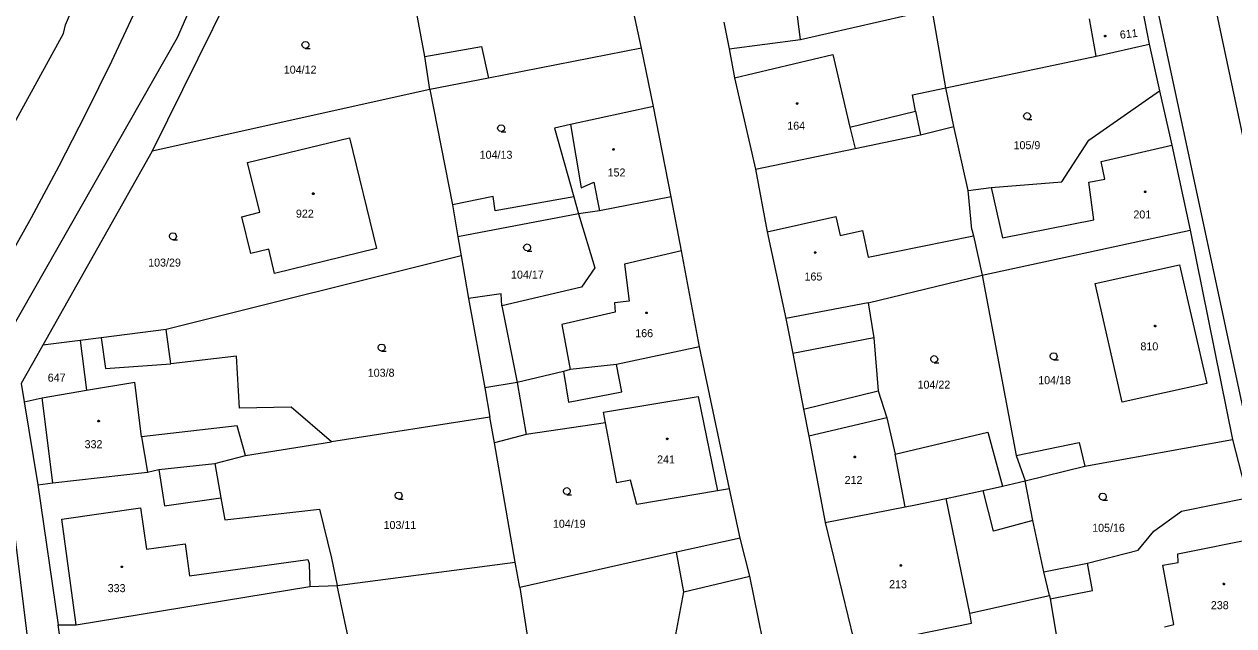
# Model space of a CAD drawing. Extents: x -757994 to -755874, y -1047691 to -1046119.
# Drawn here: x -756803.8 to -756675.3, y -1047083.2 to -1047019.3 of the extents above; entities that cross this region are included whole.
import ezdxf

# ---------------------------------------------------------------- set-up
doc = ezdxf.new("R2010")
doc.units = 0
doc.layers.add('katastrální mapa', color=7, linetype='Continuous')

msp = doc.modelspace()

# ---------------------------------------------------------------- linework, layer by layer
at = {"layer": 'katastrální mapa'}
for p, q in [((-756701.95, -1046901.14), (-756668.39, -1047059.3)), ((-756707.71, -1046903.74), (-756665.23, -1047102.74)), ((-756799.4, -1047019.41), (-756785.81, -1046987.62)), ((-756776.48, -1046995.54), (-756787.52, -1047020.76)), ((-756780.89, -1047014.02), (-756790.18, -1047032.81)), ((-756761.2, -1047022.76), (-756762.53, -1047015.73)), ((-756738.2, -1047021.87), (-756739.44, -1047016.08)), ((-756721.32, -1047020.94), (-756721.78, -1047017.37)), ((-756721.32, -1047020.94), (-756707.32, -1047017.76)), ((-756705.85, -1047026.09), (-756707.32, -1047017.76)), ((-756685, -1047017.62), (-756684.26, -1047021.44)), ((-756799.59, -1047020.32), (-756799.4, -1047019.41)), ((-756729.44, -1047019.12), (-756728.9, -1047021.94)), ((-756689.9, -1047022.72), (-756690.59, -1047018.75)), ((-756809.98, -1047039.19), (-756799.59, -1047020.32)), ((-756787.52, -1047020.76), (-756807.3, -1047055.47)), ((-756761.2, -1047022.76), (-756755.2, -1047021.69)), ((-756755.2, -1047021.69), (-756754.46, -1047025.07)), ((-756738.2, -1047021.87), (-756754.46, -1047025.07)), ((-756736.91, -1047028.06), (-756738.2, -1047021.87)), ((-756728.9, -1047021.94), (-756721.32, -1047020.94)), ((-756728.9, -1047021.94), (-756728.31, -1047025.02)), ((-756689.9, -1047022.72), (-756684.26, -1047021.44)), ((-756684.26, -1047021.44), (-756683.15, -1047026.41)), ((-756760.69, -1047026.26), (-756761.2, -1047022.76)), ((-756728.31, -1047025.02), (-756717.88, -1047022.55)), ((-756717.88, -1047022.55), (-756716.05, -1047030.25)), ((-756705.85, -1047026.09), (-756689.9, -1047022.72)), ((-756754.46, -1047025.07), (-756760.69, -1047026.26)), ((-756728.31, -1047025.02), (-756726.09, -1047034.74)), ((-756760.69, -1047026.26), (-756790.18, -1047032.81)), ((-756760.69, -1047026.26), (-756758.27, -1047038.5)), ((-756709.39, -1047026.83), (-756705.85, -1047026.09)), ((-756709.08, -1047028.56), (-756709.39, -1047026.83)), ((-756705, -1047030.19), (-756705.85, -1047026.09)), ((-756690.67, -1047031.63), (-756683.15, -1047026.41)), ((-756683.15, -1047026.41), (-756681.86, -1047032.17)), ((-756736.91, -1047028.06), (-756745.74, -1047029.99)), ((-756735.05, -1047037.66), (-756736.91, -1047028.06)), ((-756716.05, -1047030.25), (-756709.08, -1047028.56)), ((-756709.08, -1047028.56), (-756708.55, -1047031.06)), ((-756745.74, -1047029.99), (-756747.44, -1047030.36)), ((-756747.44, -1047030.36), (-756745.39, -1047037.65)), ((-756745.74, -1047029.99), (-756744.61, -1047036.71)), ((-756716.05, -1047030.25), (-756715.51, -1047032.52)), ((-756715.51, -1047032.52), (-756708.55, -1047031.06)), ((-756708.55, -1047031.06), (-756705, -1047030.19)), ((-756703.5, -1047037), (-756705, -1047030.19)), ((-756780.04, -1047034.01), (-756769.22, -1047031.38)), ((-756769.22, -1047031.38), (-756766.35, -1047043.16)), ((-756693.55, -1047036.07), (-756690.67, -1047031.63)), ((-756689.37, -1047033.91), (-756681.86, -1047032.17)), ((-756681.86, -1047032.17), (-756679.91, -1047041.22)), ((-756790.18, -1047032.81), (-756801.8, -1047053.43)), ((-756726.09, -1047034.74), (-756715.51, -1047032.52)), ((-756778.76, -1047039.3), (-756780.04, -1047034.01)), ((-756726.09, -1047034.74), (-756724.84, -1047041.38)), ((-756688.98, -1047035.8), (-756689.37, -1047033.91)), ((-756744.61, -1047036.71), (-756743.27, -1047036.11)), ((-756743.27, -1047036.11), (-756742.67, -1047039.16)), ((-756701.05, -1047036.67), (-756693.55, -1047036.07)), ((-756690.67, -1047036.11), (-756688.98, -1047035.8)), ((-756690.14, -1047040.09), (-756690.67, -1047036.11)), ((-756703.5, -1047037), (-756701.05, -1047036.67)), ((-756703.1, -1047041.13), (-756703.5, -1047037)), ((-756701.05, -1047036.67), (-756699.84, -1047042.02)), ((-756753.96, -1047037.61), (-756758.27, -1047038.5)), ((-756758.27, -1047038.5), (-756757.72, -1047041.91)), ((-756753.76, -1047039.14), (-756753.96, -1047037.61)), ((-756745.39, -1047037.65), (-756753.76, -1047039.14)), ((-756745.39, -1047037.65), (-756744.88, -1047039.46)), ((-756735.05, -1047037.66), (-756742.67, -1047039.16)), ((-756733.96, -1047043.4), (-756735.05, -1047037.66)), ((-756780.65, -1047039.77), (-756778.76, -1047039.3)), ((-756779.69, -1047043.67), (-756780.65, -1047039.77)), ((-756744.88, -1047039.46), (-756757.72, -1047041.91)), ((-756742.67, -1047039.16), (-756744.88, -1047039.46)), ((-756744.88, -1047039.46), (-756743.16, -1047045.2)), ((-756724.84, -1047041.38), (-756717.55, -1047039.74)), ((-756717.55, -1047039.74), (-756717.08, -1047041.76)), ((-756699.84, -1047042.02), (-756690.14, -1047040.09)), ((-756724.84, -1047041.38), (-756722.85, -1047050.58)), ((-756717.08, -1047041.76), (-756714.73, -1047041.25)), ((-756714.73, -1047041.25), (-756714.13, -1047044.07)), ((-756703.1, -1047041.13), (-756702.94, -1047041.82)), ((-756701.99, -1047045.97), (-756679.91, -1047041.22)), ((-756679.91, -1047041.22), (-756675.41, -1047063.42)), ((-756757.72, -1047041.91), (-756757.37, -1047043.94)), ((-756714.13, -1047044.07), (-756702.94, -1047041.82)), ((-756702.94, -1047041.82), (-756701.99, -1047045.97)), ((-756757.37, -1047043.94), (-756788.69, -1047051.74)), ((-756777.8, -1047043.21), (-756779.69, -1047043.67)), ((-756777.17, -1047045.79), (-756777.8, -1047043.21)), ((-756766.35, -1047043.16), (-756777.17, -1047045.79)), ((-756757.37, -1047043.94), (-756756.58, -1047048.46)), ((-756733.96, -1047043.4), (-756739.99, -1047044.8)), ((-756732.03, -1047053.61), (-756733.96, -1047043.4)), ((-756743.16, -1047045.2), (-756744.58, -1047047.24)), ((-756739.99, -1047044.8), (-756739.49, -1047048.73)), ((-756689.99, -1047046.88), (-756681.04, -1047044.88)), ((-756681.04, -1047044.88), (-756678.15, -1047057.5)), ((-756714.12, -1047048.91), (-756701.99, -1047045.97)), ((-756701.99, -1047045.97), (-756698.39, -1047065.15)), ((-756744.58, -1047047.24), (-756753.04, -1047049.24)), ((-756687.14, -1047059.47), (-756689.99, -1047046.88)), ((-756753.12, -1047047.95), (-756756.58, -1047048.46)), ((-756756.58, -1047048.46), (-756754.84, -1047057.95)), ((-756753.04, -1047049.24), (-756753.12, -1047047.95)), ((-756739.49, -1047048.73), (-756741.06, -1047048.93)), ((-756741.06, -1047048.93), (-756741.01, -1047049.93)), ((-756714.12, -1047048.91), (-756722.85, -1047050.58)), ((-756714.12, -1047048.91), (-756713.5, -1047052.65)), ((-756753.04, -1047049.24), (-756751.42, -1047057.37)), ((-756741.01, -1047049.93), (-756746.65, -1047051.21)), ((-756746.65, -1047051.21), (-756745.78, -1047056)), ((-756722.85, -1047050.58), (-756722.13, -1047054.31)), ((-756797.83, -1047052.92), (-756801.8, -1047053.43)), ((-756795.61, -1047052.63), (-756797.83, -1047052.92)), ((-756797.83, -1047052.92), (-756797.15, -1047058.21)), ((-756788.69, -1047051.74), (-756795.61, -1047052.63)), ((-756795.61, -1047052.63), (-756795.14, -1047055.89)), ((-756788.19, -1047055.4), (-756788.69, -1047051.74)), ((-756713.5, -1047052.65), (-756722.13, -1047054.31)), ((-756713.5, -1047052.65), (-756713.05, -1047058.26)), ((-756801.8, -1047053.43), (-756802.44, -1047054.55)), ((-756732.03, -1047053.61), (-756740.84, -1047055.46)), ((-756728.84, -1047068.66), (-756732.03, -1047053.61)), ((-756802.44, -1047054.55), (-756804.09, -1047057.48)), ((-756795.14, -1047055.89), (-756788.19, -1047055.4)), ((-756781.24, -1047054.59), (-756788.19, -1047055.4)), ((-756780.92, -1047060.12), (-756781.24, -1047054.59)), ((-756740.84, -1047055.46), (-756745.78, -1047056)), ((-756740.28, -1047058.39), (-756740.84, -1047055.46)), ((-756722.13, -1047054.31), (-756720.99, -1047060.2)), ((-756746.5, -1047056.22), (-756751.42, -1047057.37)), ((-756745.78, -1047056), (-756746.5, -1047056.22)), ((-756746.5, -1047056.22), (-756745.95, -1047059.48)), ((-756804.09, -1047057.48), (-756803.77, -1047059.45)), ((-756797.15, -1047058.21), (-756792.02, -1047057.33)), ((-756791.33, -1047063.16), (-756792.02, -1047057.33)), ((-756751.42, -1047057.37), (-756754.84, -1047057.95)), ((-756754.84, -1047057.95), (-756754.32, -1047061.05)), ((-756751.42, -1047057.37), (-756750.45, -1047062.92)), ((-756678.15, -1047057.5), (-756687.14, -1047059.47)), ((-756803.77, -1047059.45), (-756801.87, -1047059.02)), ((-756801.87, -1047059.02), (-756797.15, -1047058.21)), ((-756800.73, -1047068.04), (-756801.87, -1047059.02)), ((-756745.95, -1047059.48), (-756740.28, -1047058.39)), ((-756742.22, -1047060.54), (-756732.17, -1047058.86)), ((-756732.17, -1047058.86), (-756730.12, -1047068.88)), ((-756720.99, -1047060.2), (-756713.05, -1047058.26)), ((-756713.05, -1047058.26), (-756712.13, -1047061.13)), ((-756803.77, -1047059.45), (-756802.33, -1047068.26)), ((-756775.43, -1047059.99), (-756780.92, -1047060.12)), ((-756771.13, -1047063.67), (-756775.43, -1047059.99)), ((-756742.01, -1047061.67), (-756742.22, -1047060.54)), ((-756720.99, -1047060.2), (-756720.43, -1047063.09)), ((-756797.61, -1047131.45), (-756806.3, -1047061.1)), ((-756754.32, -1047061.05), (-756771.13, -1047063.67)), ((-756753.8, -1047063.79), (-756754.32, -1047061.05)), ((-756742.01, -1047061.67), (-756750.45, -1047062.92)), ((-756740.82, -1047068.03), (-756742.01, -1047061.67)), ((-756712.13, -1047061.13), (-756720.43, -1047063.09)), ((-756712.13, -1047061.13), (-756711.24, -1047065)), ((-756781.17, -1047061.99), (-756791.33, -1047063.16)), ((-756791.33, -1047063.16), (-756790.67, -1047066.9)), ((-756780.25, -1047065.14), (-756781.17, -1047061.99)), ((-756750.45, -1047062.92), (-756753.8, -1047063.79)), ((-756720.43, -1047063.09), (-756718.67, -1047072.24)), ((-756711.24, -1047065), (-756701.41, -1047062.67)), ((-756701.41, -1047062.67), (-756699.84, -1047068.39)), ((-756780.25, -1047065.14), (-756771.13, -1047063.67)), ((-756751.62, -1047076.46), (-756753.8, -1047063.79)), ((-756698.39, -1047065.15), (-756691.71, -1047063.77)), ((-756691.71, -1047063.77), (-756691.1, -1047066.27)), ((-756691.1, -1047066.27), (-756675.41, -1047063.42)), ((-756675.41, -1047063.42), (-756673.83, -1047069.63)), ((-756783.52, -1047065.97), (-756780.25, -1047065.14)), ((-756710.2, -1047070.6), (-756711.24, -1047065)), ((-756698.39, -1047065.15), (-756697.42, -1047067.82)), ((-756800.73, -1047068.04), (-756790.67, -1047066.9)), ((-756790.67, -1047066.9), (-756789.46, -1047066.61)), ((-756789.46, -1047066.61), (-756783.52, -1047065.97)), ((-756789.46, -1047066.61), (-756788.89, -1047070.47)), ((-756783.52, -1047065.97), (-756782.9, -1047069.63)), ((-756697.42, -1047067.82), (-756691.1, -1047066.27)), ((-756802.33, -1047068.26), (-756800.73, -1047068.04)), ((-756802.33, -1047068.26), (-756800.17, -1047083.12)), ((-756739.37, -1047067.75), (-756740.82, -1047068.03)), ((-756738.68, -1047070.33), (-756739.37, -1047067.75)), ((-756701.9, -1047068.86), (-756699.84, -1047068.39)), ((-756699.84, -1047068.39), (-756697.42, -1047067.82)), ((-756696.62, -1047072.05), (-756697.42, -1047067.82)), ((-756788.89, -1047070.47), (-756782.9, -1047069.63)), ((-756782.9, -1047069.63), (-756782.48, -1047071.96)), ((-756730.12, -1047068.88), (-756738.68, -1047070.33)), ((-756728.84, -1047068.66), (-756730.12, -1047068.88)), ((-756727.73, -1047073.91), (-756728.84, -1047068.66)), ((-756705.83, -1047069.69), (-756701.9, -1047068.86)), ((-756700.81, -1047073.17), (-756701.9, -1047068.86)), ((-756680.82, -1047071.04), (-756673.83, -1047069.63)), ((-756799.78, -1047071.9), (-756791.44, -1047070.7)), ((-756791.44, -1047070.7), (-756790.78, -1047075.08)), ((-756782.48, -1047071.96), (-756772.4, -1047070.84)), ((-756772.4, -1047070.84), (-756771.14, -1047076.04)), ((-756718.67, -1047072.24), (-756710.2, -1047070.6)), ((-756710.2, -1047070.6), (-756709.26, -1047070.42)), ((-756709.26, -1047070.42), (-756705.83, -1047069.69)), ((-756703.33, -1047081.9), (-756705.83, -1047069.69)), ((-756798.25, -1047083.13), (-756799.78, -1047071.9)), ((-756718.67, -1047072.24), (-756715.68, -1047084.65)), ((-756696.62, -1047072.05), (-756700.81, -1047073.17)), ((-756695.45, -1047077.48), (-756696.62, -1047072.05)), ((-756683.76, -1047073.16), (-756680.82, -1047071.04)), ((-756685.42, -1047075.2), (-756683.76, -1047073.16)), ((-756790.78, -1047075.08), (-756786.68, -1047074.51)), ((-756786.68, -1047074.51), (-756786.2, -1047077.93)), ((-756727.73, -1047073.91), (-756734.49, -1047075.42)), ((-756726.68, -1047077.94), (-756727.73, -1047073.91)), ((-756681.22, -1047075.59), (-756672.76, -1047073.87)), ((-756771.14, -1047076.04), (-756770.54, -1047078.93)), ((-756734.49, -1047075.42), (-756751.14, -1047079.14)), ((-756733.7, -1047079.62), (-756734.49, -1047075.42)), ((-756690.82, -1047076.57), (-756685.42, -1047075.2)), ((-756681.17, -1047076.51), (-756681.22, -1047075.59)), ((-756786.2, -1047077.93), (-756773.64, -1047076.18)), ((-756773.64, -1047076.18), (-756773.52, -1047076.61)), ((-756773.52, -1047076.61), (-756773.43, -1047079.05)), ((-756770.54, -1047078.93), (-756751.62, -1047076.46)), ((-756751.14, -1047079.14), (-756751.62, -1047076.46)), ((-756695.45, -1047077.48), (-756690.82, -1047076.57)), ((-756690.3, -1047079.49), (-756690.82, -1047076.57)), ((-756682.82, -1047076.79), (-756681.17, -1047076.51)), ((-756681.63, -1047083.1), (-756682.82, -1047076.79)), ((-756733.7, -1047079.62), (-756726.68, -1047077.94)), ((-756725.3, -1047084.75), (-756726.68, -1047077.94)), ((-756694.85, -1047080.01), (-756695.45, -1047077.48)), ((-756798.25, -1047083.13), (-756773.43, -1047079.05)), ((-756773.43, -1047079.05), (-756770.54, -1047078.93)), ((-756768.53, -1047088.21), (-756770.54, -1047078.93)), ((-756751.14, -1047079.14), (-756747.9, -1047099.85)), ((-756734.67, -1047084.72), (-756733.7, -1047079.62)), ((-756694.77, -1047080.37), (-756690.3, -1047079.49)), ((-756703.33, -1047081.9), (-756694.85, -1047080.01)), ((-756694.85, -1047080.01), (-756694.77, -1047080.37)), ((-756694.77, -1047080.37), (-756693.94, -1047085.44)), ((-756703.12, -1047082.93), (-756703.33, -1047081.9)), ((-756799.16, -1047090.3), (-756800.17, -1047083.12)), ((-756800.17, -1047083.12), (-756798.25, -1047083.13)), ((-756715.51, -1047085.47), (-756703.12, -1047082.93)), ((-756682.64, -1047083.35), (-756681.63, -1047083.1))]:
    msp.add_line(p, q, dxfattribs=at)
for points in [[(-756836.87, -1047091.03), (-756833.57, -1047086.8), (-756829.82, -1047081.82), (-756826.16, -1047076.78), (-756822.58, -1047071.68), (-756819.1, -1047066.52), (-756815.7, -1047061.3), (-756812.39, -1047056.03), (-756809.17, -1047050.69), (-756806.05, -1047045.31), (-756803.01, -1047039.87), (-756800.07, -1047034.38), (-756797.23, -1047028.84), (-756794.48, -1047023.25), (-756792.19, -1047018.39), (-756789.97, -1047013.53), (-756787.51, -1047007.87), (-756785.14, -1047002.18), (-756782.87, -1046996.44), (-756780.99, -1046991.44)], [(-756773.89, -1047021.89), (-756774.08, -1047021.84), (-756774.22, -1047021.71), (-756774.27, -1047021.52), (-756774.22, -1047021.34), (-756774.08, -1047021.2), (-756773.9, -1047021.15), (-756773.71, -1047021.2), (-756773.58, -1047021.34), (-756773.53, -1047021.53), (-756773.58, -1047021.72), (-756773.71, -1047021.85), (-756773.9, -1047021.9), (-756773.4, -1047021.9)], [(-756697.22, -1047029.45), (-756697.41, -1047029.4), (-756697.54, -1047029.26), (-756697.6, -1047029.08), (-756697.54, -1047028.9), (-756697.41, -1047028.76), (-756697.23, -1047028.71), (-756697.04, -1047028.76), (-756696.91, -1047028.9), (-756696.85, -1047029.09), (-756696.91, -1047029.27), (-756697.04, -1047029.41), (-756697.23, -1047029.46), (-756696.73, -1047029.46)], [(-756753.11, -1047030.74), (-756753.3, -1047030.69), (-756753.44, -1047030.55), (-756753.48, -1047030.37), (-756753.44, -1047030.19), (-756753.3, -1047030.05), (-756753.11, -1047030), (-756752.93, -1047030.05), (-756752.79, -1047030.19), (-756752.74, -1047030.38), (-756752.79, -1047030.57), (-756752.93, -1047030.7), (-756753.12, -1047030.75), (-756752.62, -1047030.75)], [(-756787.97, -1047042.22), (-756788.16, -1047042.17), (-756788.29, -1047042.03), (-756788.35, -1047041.85), (-756788.29, -1047041.67), (-756788.16, -1047041.53), (-756787.98, -1047041.48), (-756787.79, -1047041.53), (-756787.66, -1047041.67), (-756787.6, -1047041.86), (-756787.66, -1047042.04), (-756787.79, -1047042.18), (-756787.98, -1047042.23), (-756787.48, -1047042.23)], [(-756750.34, -1047043.41), (-756750.53, -1047043.36), (-756750.67, -1047043.23), (-756750.72, -1047043.04), (-756750.67, -1047042.86), (-756750.53, -1047042.72), (-756750.35, -1047042.67), (-756750.16, -1047042.72), (-756750.02, -1047042.86), (-756749.98, -1047043.05), (-756750.02, -1047043.24), (-756750.16, -1047043.37), (-756750.35, -1047043.42), (-756749.85, -1047043.42)], [(-756765.8, -1047054.04), (-756765.99, -1047053.99), (-756766.12, -1047053.86), (-756766.18, -1047053.67), (-756766.12, -1047053.49), (-756765.99, -1047053.35), (-756765.81, -1047053.3), (-756765.62, -1047053.35), (-756765.49, -1047053.49), (-756765.44, -1047053.68), (-756765.49, -1047053.87), (-756765.62, -1047054), (-756765.81, -1047054.05), (-756765.31, -1047054.05)], [(-756694.4, -1047054.97), (-756694.59, -1047054.92), (-756694.73, -1047054.78), (-756694.78, -1047054.6), (-756694.73, -1047054.42), (-756694.59, -1047054.28), (-756694.41, -1047054.23), (-756694.22, -1047054.28), (-756694.09, -1047054.42), (-756694.04, -1047054.61), (-756694.09, -1047054.79), (-756694.22, -1047054.93), (-756694.41, -1047054.98), (-756693.91, -1047054.98)], [(-756707.09, -1047055.27), (-756707.28, -1047055.22), (-756707.42, -1047055.09), (-756707.47, -1047054.9), (-756707.42, -1047054.72), (-756707.28, -1047054.58), (-756707.1, -1047054.53), (-756706.91, -1047054.58), (-756706.77, -1047054.72), (-756706.73, -1047054.91), (-756706.77, -1047055.1), (-756706.91, -1047055.23), (-756707.1, -1047055.28), (-756706.6, -1047055.28)], [(-756763.99, -1047069.77), (-756764.18, -1047069.72), (-756764.32, -1047069.59), (-756764.36, -1047069.4), (-756764.32, -1047069.22), (-756764.18, -1047069.08), (-756763.99, -1047069.03), (-756763.81, -1047069.08), (-756763.68, -1047069.22), (-756763.62, -1047069.41), (-756763.68, -1047069.6), (-756763.81, -1047069.73), (-756764, -1047069.78), (-756763.5, -1047069.78)], [(-756746.12, -1047069.29), (-756746.31, -1047069.24), (-756746.45, -1047069.11), (-756746.49, -1047068.92), (-756746.45, -1047068.74), (-756746.31, -1047068.6), (-756746.12, -1047068.55), (-756745.94, -1047068.6), (-756745.8, -1047068.74), (-756745.76, -1047068.93), (-756745.8, -1047069.12), (-756745.94, -1047069.25), (-756746.13, -1047069.3), (-756745.63, -1047069.3)], [(-756689.19, -1047069.87), (-756689.38, -1047069.82), (-756689.51, -1047069.69), (-756689.57, -1047069.5), (-756689.51, -1047069.32), (-756689.38, -1047069.18), (-756689.2, -1047069.13), (-756689.01, -1047069.18), (-756688.88, -1047069.32), (-756688.83, -1047069.51), (-756688.88, -1047069.7), (-756689.01, -1047069.83), (-756689.2, -1047069.88), (-756688.7, -1047069.88)]]:
    msp.add_lwpolyline(points, dxfattribs=at)
for points in [[(-756688.93, -1047020.5), (-756688.88, -1047020.51), (-756688.85, -1047020.56), (-756688.85, -1047020.59), (-756688.85, -1047020.64), (-756688.9, -1047020.67), (-756688.93, -1047020.68), (-756688.98, -1047020.66), (-756689.01, -1047020.63), (-756689.02, -1047020.59), (-756689.01, -1047020.54), (-756688.97, -1047020.51)], [(-756721.65, -1047027.67), (-756721.6, -1047027.68), (-756721.58, -1047027.72), (-756721.57, -1047027.75), (-756721.58, -1047027.79), (-756721.61, -1047027.83), (-756721.65, -1047027.84), (-756721.7, -1047027.82), (-756721.73, -1047027.79), (-756721.74, -1047027.75), (-756721.73, -1047027.71), (-756721.69, -1047027.67)], [(-756741.16, -1047032.54), (-756741.11, -1047032.55), (-756741.09, -1047032.6), (-756741.08, -1047032.63), (-756741.09, -1047032.68), (-756741.12, -1047032.71), (-756741.16, -1047032.72), (-756741.21, -1047032.7), (-756741.24, -1047032.67), (-756741.25, -1047032.63), (-756741.24, -1047032.59), (-756741.2, -1047032.55)], [(-756773.07, -1047037.24), (-756773.02, -1047037.25), (-756772.99, -1047037.3), (-756772.98, -1047037.33), (-756772.99, -1047037.38), (-756773.03, -1047037.41), (-756773.07, -1047037.42), (-756773.11, -1047037.4), (-756773.15, -1047037.37), (-756773.16, -1047037.33), (-756773.15, -1047037.28), (-756773.1, -1047037.25)], [(-756684.69, -1047037.03), (-756684.64, -1047037.04), (-756684.61, -1047037.09), (-756684.6, -1047037.12), (-756684.61, -1047037.17), (-756684.66, -1047037.2), (-756684.69, -1047037.21), (-756684.73, -1047037.19), (-756684.76, -1047037.16), (-756684.77, -1047037.12), (-756684.76, -1047037.08), (-756684.72, -1047037.04)], [(-756719.75, -1047043.49), (-756719.7, -1047043.5), (-756719.68, -1047043.55), (-756719.67, -1047043.58), (-756719.68, -1047043.62), (-756719.72, -1047043.66), (-756719.75, -1047043.67), (-756719.79, -1047043.65), (-756719.83, -1047043.62), (-756719.84, -1047043.58), (-756719.83, -1047043.53), (-756719.78, -1047043.5)], [(-756737.65, -1047049.9), (-756737.6, -1047049.91), (-756737.58, -1047049.95), (-756737.57, -1047049.98), (-756737.58, -1047050.02), (-756737.61, -1047050.06), (-756737.65, -1047050.07), (-756737.7, -1047050.05), (-756737.73, -1047050.02), (-756737.74, -1047049.98), (-756737.73, -1047049.94), (-756737.69, -1047049.9)], [(-756683.63, -1047051.29), (-756683.58, -1047051.3), (-756683.55, -1047051.35), (-756683.54, -1047051.38), (-756683.55, -1047051.43), (-756683.6, -1047051.46), (-756683.63, -1047051.47), (-756683.68, -1047051.45), (-756683.71, -1047051.42), (-756683.72, -1047051.38), (-756683.71, -1047051.34), (-756683.67, -1047051.3)], [(-756795.87, -1047061.4), (-756795.82, -1047061.41), (-756795.79, -1047061.45), (-756795.78, -1047061.48), (-756795.79, -1047061.52), (-756795.84, -1047061.56), (-756795.87, -1047061.57), (-756795.92, -1047061.55), (-756795.95, -1047061.52), (-756795.96, -1047061.48), (-756795.95, -1047061.44), (-756795.91, -1047061.4)], [(-756735.46, -1047063.28), (-756735.41, -1047063.29), (-756735.39, -1047063.34), (-756735.38, -1047063.37), (-756735.39, -1047063.42), (-756735.43, -1047063.45), (-756735.46, -1047063.46), (-756735.5, -1047063.44), (-756735.53, -1047063.41), (-756735.54, -1047063.37), (-756735.53, -1047063.33), (-756735.49, -1047063.29)], [(-756715.54, -1047065.21), (-756715.49, -1047065.22), (-756715.47, -1047065.26), (-756715.46, -1047065.29), (-756715.47, -1047065.34), (-756715.51, -1047065.37), (-756715.54, -1047065.38), (-756715.59, -1047065.36), (-756715.61, -1047065.33), (-756715.62, -1047065.29), (-756715.61, -1047065.25), (-756715.58, -1047065.21)], [(-756793.4, -1047076.89), (-756793.35, -1047076.9), (-756793.33, -1047076.94), (-756793.32, -1047076.97), (-756793.33, -1047077.01), (-756793.36, -1047077.05), (-756793.4, -1047077.05), (-756793.45, -1047077.04), (-756793.48, -1047077.01), (-756793.49, -1047076.97), (-756793.48, -1047076.93), (-756793.44, -1047076.89)], [(-756710.65, -1047076.73), (-756710.6, -1047076.74), (-756710.58, -1047076.78), (-756710.57, -1047076.81), (-756710.58, -1047076.86), (-756710.61, -1047076.89), (-756710.65, -1047076.9), (-756710.7, -1047076.88), (-756710.73, -1047076.85), (-756710.74, -1047076.81), (-756710.73, -1047076.77), (-756710.69, -1047076.73)], [(-756676.33, -1047078.7), (-756676.28, -1047078.71), (-756676.25, -1047078.75), (-756676.24, -1047078.78), (-756676.25, -1047078.83), (-756676.29, -1047078.86), (-756676.33, -1047078.87), (-756676.38, -1047078.85), (-756676.41, -1047078.82), (-756676.42, -1047078.78), (-756676.41, -1047078.74), (-756676.36, -1047078.7)]]:
    msp.add_lwpolyline(points, close=True, dxfattribs=at)

# ---------------------------------------------------------------- texts
msp.add_text('611', height=0.85, rotation=6.5317, dxfattribs=at).set_placement((-756687.33, -1047020.88))
for s, p in [('104/12', (-756776.2, -1047024.58)), ('164', (-756722.71, -1047030.53)), ('105/9', (-756698.67, -1047032.6)), ('104/13', (-756755.39, -1047033.62)), ('152', (-756741.8, -1047035.5)), ('922', (-756774.91, -1047039.87)), ('201', (-756685.94, -1047039.96)), ('103/29', (-756790.61, -1047045.07)), ('104/17', (-756752.06, -1047046.35)), ('165', (-756720.88, -1047046.55)), ('166', (-756738.86, -1047052.57)), ('810', (-756685.19, -1047053.97)), ('647', (-756801.28, -1047057.29)), ('103/8', (-756767.28, -1047056.77)), ('104/18', (-756696.05, -1047057.56)), ('104/22', (-756708.87, -1047058.04)), ('332', (-756797.36, -1047064.36)), ('241', (-756736.54, -1047065.98)), ('212', (-756716.62, -1047068.16)), ('103/11', (-756765.6, -1047072.94)), ('104/19', (-756747.61, -1047072.81)), ('105/16', (-756690.32, -1047073.24)), ('213', (-756711.89, -1047079.23)), ('333', (-756794.91, -1047079.65)), ('238', (-756677.71, -1047081.46))]:
    msp.add_text(s, height=0.85, dxfattribs=at).set_placement(p)

doc.saveas('drawing.dxf')
